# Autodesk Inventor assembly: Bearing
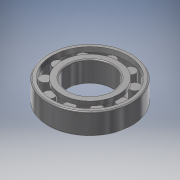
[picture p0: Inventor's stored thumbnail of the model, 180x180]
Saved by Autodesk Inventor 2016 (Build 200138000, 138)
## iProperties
ClientObjectVersion: 1
Created: 2015-08
Part Number: Bearing
Document SubType Name: Assembly
Designer: Ugljesa
Author: Ugljesa
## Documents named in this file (2)
- C:\Users\Ugljesa\Desktop\Turbokompr\Assembly1\Design Accelerator\Bearing1.iam
- C:\Users\Ugljesa\Documents\Inventor\Content Center Files\R2016\en-US\BS 292 (V)\BS 292_ Part 1 - N 1005 - 25 x 47 x 12.ipt
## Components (1 placed, 1 different names)
1. BS 292: Part 1 (V) (Metric) N 1005 - 25 x 47 x 12:1
